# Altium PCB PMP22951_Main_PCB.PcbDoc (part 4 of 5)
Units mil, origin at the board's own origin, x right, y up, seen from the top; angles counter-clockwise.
Board outline 6643.5 x 4153.54 mil, 6 copper layers (Top Layer, Signal Layer 1, Signal Layer 2, Signal Layer 3, Signal Layer 4, Bottom Layer), stack 65.8 mil thick; 139 components, 80 nets, 687 pads, 417 vias.
Unrouted connection lines stored in the file: 2.
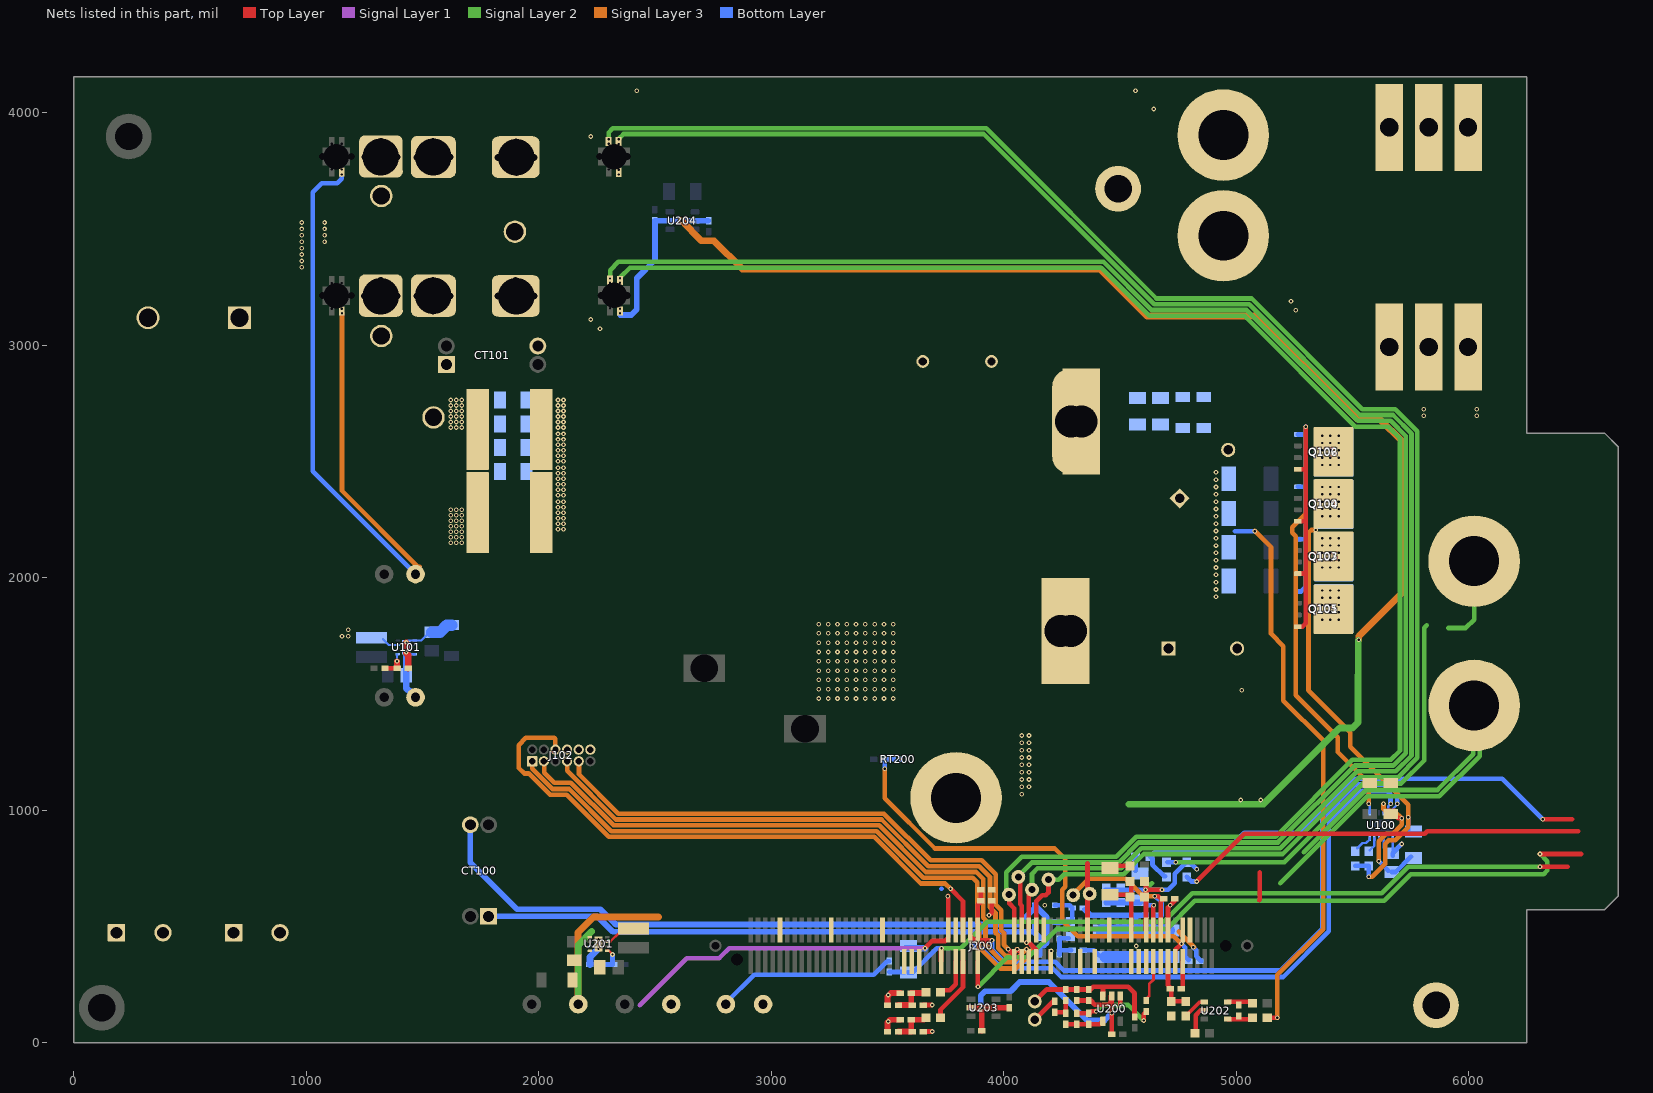
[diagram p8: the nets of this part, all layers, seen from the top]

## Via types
v1: diameter 20, hole 10, Top Layer to Bottom Layer, 409 vias
v2: diameter 19.68, hole 7.87, Top Layer to Bottom Layer, 7 vias
v3: diameter 24, hole 8, Top Layer to Bottom Layer, tented both sides, 1 vias

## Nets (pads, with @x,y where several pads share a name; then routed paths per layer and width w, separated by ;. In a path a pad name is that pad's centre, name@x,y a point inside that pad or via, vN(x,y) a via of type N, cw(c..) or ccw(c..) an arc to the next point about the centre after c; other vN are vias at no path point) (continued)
54V2: C115.1 Q100.5 Q100.6 Q100.7 Q100.8 Q100.9@5418.5,2316.93 Q101.5 Q101.6 Q101.7 Q101.8 Q101.9@5418.5,1864.17 Q102.5 Q102.6 Q102.7 Q102.8 Q102.9@5418.5,2541.34 Q103.5 Q103.6 Q103.7 Q103.8 Q103.9@5418.5,2092.52 Q104.5 Q104.6 Q104.7 Q104.8 Q104.9@5419.49,2315.32 Q105.5 Q105.6 Q105.7 Q105.8 Q105.9@5419.49,1865.32 Q106.5 Q106.6 Q106.7 Q106.8 Q106.9@5419.49,2540.32 Q107.5 Q107.6 Q107.7 Q107.8 Q107.9@5419.49,2090.32 R102.1 R108.2 R116.2 Vout+.1 | length 4053.5
  Signal Layer 2 w20: v1(4740,775) 5207.84,775 5547.46,1114.61 5710,1114.61 5808.77,1213.39 5808.77,1783.77 5820,1795 ; 5913.39,1783.46 5988.19,1783.46 6023.62,1818.9 Vout+.1@6023.62,1933.07
  Signal Layer 3 w20: v1(5342.52,2204.72) 5322.83,2204.72 5311.02,2192.91 5311.02,1515.75 5491.57,1335.2 5491.57,1272.21 5740.16,1023.62 v1(5740.16,968.5) 5740.16,926.38 5684.41,870.64 5656.85,870.64 5641.17,854.96 5641.17,768.34 5585.43,712.6 v1@5574.8,712.6
  Bottom Layer w20: R102.1@4705,775 v1(4740,775) ; R116.2@5511.81,759.84 C115.1@5562.99,759.84 ; v1(5570.87,712.6) C115.1@5570.87,759.84 ; R108.2@5740.16,909.45 v1(5740.16,968.5)
  other v1: 5370.08,1818.9 5405.51,1818.9 5440.94,1818.9 5370.08,1850.39 5405.51,1850.39 5440.94,1850.39 5370.08,1881.89 5405.51,1881.89 5440.94,1881.89 5370.08,1913.39 5405.51,1913.39 5440.94,1913.39 5370.08,1944.88 5405.51,1944.88 5440.94,1944.88 5370.08,2043.31 5405.51,2043.31 5440.94,2043.31 5370.08,2074.8 5405.51,2074.8 5440.94,2074.8 5370.08,2106.3 5405.51,2106.3 5440.94,2106.3 5370.08,2137.8 5405.51,2137.8 5440.94,2137.8 5370.08,2169.29 5405.51,2169.29 5440.94,2169.29 5370.08,2263.78 5405.51,2263.78 5440.94,2263.78 5370.08,2295.28 5405.51,2295.28 5440.94,2295.28 5370.08,2326.77 5405.51,2326.77 5440.94,2326.77 5370.08,2358.27 5405.51,2358.27 5440.94,2358.27 5370.08,2389.76 5405.51,2389.76 5440.94,2389.76 5370.08,2484.25 5405.51,2484.25 5440.94,2484.25 5370.08,2515.75 5405.51,2515.75 5440.94,2515.75 5370.08,2547.24 5405.51,2547.24 5440.94,2547.24 5370.08,2578.74 5405.51,2578.74 5440.94,2578.74 5370.08,2610.24 5405.51,2610.24 5440.94,2610.24
54VLS-EN: J200.58 | length 3027.1
  Top Layer w20: J200.58@3888.07,349.53 3888.07,241.85 v1(3889.76,240.16) ; v1(6307.09,811.02) 6484.25,811.02
  Signal Layer 2 w20: v1(3889.76,240.16) 4015.75,366.14 4106.3,366.14 4228.35,488.19 4700.79,488.19 4822.83,610.24 5637.8,610.24 5751.97,724.41 6322.83,724.41 6338.58,740.16 6338.58,779.53 v1(6307.09,811.02)
ACTIVE_EMI_SENSE_PSFB: J200.34
AD_IBUS: J200.24
COIL_SEC_N: C207.2 C209.1 pad.1@4133.86,177.17 R215.1 R219.2 U200.3 | length 597.2
  Top Layer w20: pad.1@4129.92,173.23 4185.04,228.35 C207.2@4267.72,228.35 C209.1@4314.96,228.35 4318.9,228.35 R219.2@4366.14,228.35 4374.02,228.35 4385.83,240.16 4535.43,240.16 4562.99,212.6 R215.1@4562.99,118.11 ; U200.3@4427.17,199.8 4427.17,230.32
COIL_SEC_P: pad.2 R217.1 | length 124.8
  Top Layer w20: pad.2@4129.92,94.49 4212.6,177.17 R217.1@4220.47,177.17
CS+: CT100.1 CT101.1 D201.2 D203.1 | length 2453.9
  Bottom Layer w25: CT100.1@1784.37,543.15 2252.13,543.15 2318.9,476.38 4129.92,476.38 4133.86,472.44 ; D201.2@4133.86,519.68 4133.86,472.44 ; D203.1@4153.54,452.76 4133.86,472.44
CS-: CT100.3 CT101.3 D200.2 D202.1 | length 2999.9
  Bottom Layer w25: CT100.3@1705,930 1705,775 1906.95,573.05 2264.51,573.05 2327.56,510 ; 2312.77,527.77 2332.15,508.38 4063.5,508.38 D200.2@4133.86,578.74 ; D200.2@4133.86,590.55 4185.54,538.87 4185.54,439.5 4184.85,438.81 4184.85,428.93 4173.43,417.51 4161.42,417.51 4153.54,409.63 D202.1@4153.54,377.95
DAC_OUT: J200.9
FAN_CTRL: J200.63
FAN_FB: J200.20
IHV_FB: C202.1 J200.15 pad.1@4299.21,633.86 R205.2 | length 710.4
  Top Layer w20: v1(4649.61,629.92) 4665.35,629.92 C202.1@4681.1,614.17 ; J200.15@4675.47,483.39 4675.47,604.61 C202.1@4685.04,614.17
  Signal Layer 3 w20: pad.1@4299.21,633.86 4299.21,637.8 4366.42,705 4525,705 4600,630 v1@4650,630
  Bottom Layer w20: v1(4649.61,629.92) 4652.36,629.92 4679.92,602.36 4679.92,545.08 4655.08,545.08 R205.2@4655,545
ILV_FB: C213.2 J200.14 R224.1 R227.2 | length 225.2
  Top Layer w20: J200.14@4706.97,349.53 4706.97,245.79 C213.2@4716.54,236.22 ; C213.2@4720.47,232.28 4720.47,181.1 4724.41,177.17 R224.1@4775.59,177.17
ILV_ZCD: J200.18 R218.2 | length 172.9
  Top Layer w12: R218.2@4614.17,188.98 4625.98,200.79 4625.98,251.97 4643.98,269.96 J200.18@4643.98,349.53
Iout_SNS: C110.1 C111.1 C117.1 C118.1 L100.2 pad.1@4334.33,2671.85 R100.1 R101.1 R103.2 R104.2 R105.1 R106.1 R226.1 | length 2426.6
  Top Layer w20: R226.1@5133.86,106.3 v1(5177.17,106.3)
  Signal Layer 3 w20: v1@5079.93,2200.79 5150.17,2130.55 5150.17,1758.21 5203.02,1705.35 5203.02,1471.01 5374.57,1299.46 5374.57,488.19 5177.17,290.78 v1(5177.17,106.3)
  Bottom Layer w20: 4995,2200 v1(5080,2200)
  other v1: 4913.39,1917.32 4913.39,1948.82 4913.39,1980.32 4913.39,2011.81 4913.39,2043.31 4913.39,2074.8 4913.39,2106.3 4913.39,2137.8 4913.39,2169.29 4913.39,2200.79 4913.39,2232.28 4913.39,2263.78 4913.39,2295.28 4913.39,2326.77 4913.39,2358.27 4913.39,2389.76 4913.39,2421.26 4913.39,2452.76
LEG1_FLT: R200.2 | length 39.4
  Top Layer w20: R200.2@3653.54,47.24 v1(3692.91,47.24)
LEG1_HS: J200.49 pad.1@2300.65,3866.04 pad.1@4192.91,700.79 | length 7500.6
  Top Layer w20: J200.49@4140.04,483.39 4140.04,608.54 4165.35,633.86 4181.1,633.86 4192.91,645.67 pad.1@4192.91,688.98
  Signal Layer 2 w20: v1(2300.65,3886.16) 2300.65,3914.82 2318.9,3933.07 3925.2,3933.07 4657.48,3200.79 5066.93,3200.79 5543.31,2724.41 5685.04,2724.41 5779.53,2629.92 5779.53,1224.41 5696.85,1141.73 5531.5,1141.73 5200.79,811.02 4602.36,811.02 4515.75,724.41 4259.84,724.41 4236.22,700.79 pad.1@4192.91,700.79
LEG1_LS: J200.51 pad.1@2343.7,3865.04 pad.1@4122.05,657.48 | length 7421.6
  Top Layer w20: J200.51@4108.54,483.39 pad.1@4108.54,636.1
  Signal Layer 2 w20: pad.1@2346.46,3889.76 2364.86,3908.17 3914.88,3908.17 4647.17,3175.89 5056.62,3175.89 5532.99,2699.51 5674.73,2699.51 5754.63,2619.61 5754.63,1234.72 5686.54,1166.63 5520.96,1166.63 5190.25,835.92 4592.05,835.92 4505.43,749.31 4145.67,749.31 4122.05,725.69 pad.1@4122.05,657.48 pad.1@4114.17,648.01 ; pad.1@4110.24,637.8 pad.1@4120.71,637.8
  other v1: 2343.7,3885.16
LEG2_FLT: R203.2 | length 35.4
  Top Layer w20: R203.2@3653.54,161.42 v1@3688.98,161.42
  other v1: 3692.91,161.42
LEG2_HS: J200.53 pad.1@2306.65,3269.04 pad.1@4062.99,712.6 | length 7255.3
  Top Layer w20: pad.1@4070.87,704.72 4070.87,594.49 4077.05,588.31 J200.53@4077.05,483.39
  Signal Layer 2 w20: pad.1@2307.09,3287.4 2307.09,3322.83 2342.74,3358.49 4429.35,3358.49 4636.85,3150.99 5046.3,3150.99 5522.68,2674.61 5664.41,2674.61 5729.73,2609.29 5729.73,1245.04 5676.22,1191.53 5510.65,1191.53 5179.94,860.82 4581.3,860.82 4494.68,774.21 4120.67,774.21 pad.1@4066.93,720.47 ; pad.1@4062.99,712.6 pad.1@4066.93,712.6
  other v3: 2306.74,3287.16
LEG2_LS: J200.55 pad.1@2349.7,3268.04 pad.1@4022.28,636.06 | length 7187.3
  Top Layer w20: pad.1@4019.69,625.98 4023.62,622.05 4023.62,598.43 4045.55,576.5 J200.55@4045.55,483.39
  Signal Layer 2 w20: pad.1@2350.39,3291.34 2392.64,3333.59 4419.04,3333.59 4626.54,3126.09 5035.99,3126.09 5512.37,2649.71 5654.1,2649.71 5704.83,2598.98 5704.83,1255.35 5665.91,1216.43 5500.34,1216.43 5169.63,885.72 4570.98,885.72 4484.37,799.11 4078.64,799.11 4011.81,732.28 4011.81,646.54 pad.1@4022.28,636.06 ; pad.1@4027.56,653.54 pad.1@4031.5,653.54
  other v1: 2349.7,3288.16
LEG3_HS: J102.1 J200.50 | length 2892.4
  Top Layer w20: v1(4098.43,429.13) 4110.24,429.13 4140.04,399.33 J200.50@4140.04,349.53
  Signal Layer 3 w20: J102.1@1972.44,1212.6 1972.44,1177.38 2058.95,1090.88 2130.25,1090.88 2311.58,909.55 3453.97,909.55 3654.76,708.76 3866.14,708.76 3885.83,689.08 3885.83,519.68 3894,511.51 3894,409.88 3985.31,318.57 4053.61,318.57 4054.61,319.57 4054.84,319.57 4085.13,349.87 ; 4085.02,349.98 4125.43,390.39 4125.43,412.76 4109.05,429.13 v1(4098.43,429.13)
LEG3_LS: J102.3 J200.52 | length 2698
  Top Layer w20: J200.52@4099.05,402.13 4108.54,392.64 J200.52@4108.54,349.53
  Signal Layer 3 w20: J102.3@2022.05,1208.66 J102.3@2022.05,1210 ; J102.3@2023.62,1208.66 2023.62,1161.42 2066.93,1118.11 2138.23,1118.11 2321.89,934.45 3464.29,934.45 3665.07,733.66 3881.89,733.66 3912.11,703.45 3912.11,536.93 3922,527.04 3922,421.48 3996.9,346.57 4042.01,346.57 ; 4043.24,347.57 4097.24,401.57 v1(4098.43,401.57)
LEG4_HS: J102.7 J200.54 | length 2537
  Top Layer w20: v1(4059.06,401.57) 4077.05,383.58 J200.54@4077.05,349.53
  Signal Layer 3 w20: J102.7@2122.05,1210 2122.05,1169.51 2332.21,959.35 3474.6,959.35 3675.39,758.56 3894.98,758.56 3940.94,712.6 3940.94,582.68 3964.57,559.06 3964.57,472.44 3976.38,460.63 3976.38,405.51 4007.87,374.02 4031.5,374.02 v1(4059.06,401.57)
LEG4_LS: J102.9 J200.56 | length 2434
  Top Layer w20: v1(4019.69,401.57) 4045.55,375.71 J200.56@4045.55,349.53
  Signal Layer 3 w20: J102.9@2172.05,1208.66 J102.9@2172.05,1210 ; J102.9@2173.23,1208.66 2173.23,1153.54 2342.52,984.25 3484.91,984.25 3685.7,783.46 3905.51,783.46 3965.84,723.13 3965.84,593.21 3989.47,569.59 3989.47,482.97 4001.28,471.16 4001.28,419.98 v1(4019.69,401.57)
NetC113_1: C113.1 C114.1 R108.1 U100.4 U100.10 | length 697.4
  Top Layer w20: C113.1@5677.17,984.25 5696.85,964.57 v1(5712.6,964.57)
  Signal Layer 3 w20: v1(5614.17,779.53) 5614.17,866.14 5645.67,897.64 5673.23,897.64 5712.6,937.01 v1(5712.6,964.57) 5681.1,996.06 5641.73,996.06 5633.86,1003.94 v1(5633.86,1027.56)
  Bottom Layer w10: v1@5614.45,779.25 U100.10@5614.45,879.02 ; U100.4@5634.13,988.46 5634.13,1016.41
  Bottom Layer w20: v1(5614.17,779.53) 5614.45,779.25 C114.1@5653.54,740.16 ; C114.1@5669.29,733.74 5686.5,733.74 R108.1@5751.97,799.21
NetC115_2: C115.2 U100.11 | length 60.5
  Bottom Layer w10: C115.2@5574.8,826.77 5594.76,846.73 U100.11@5594.76,879.02
NetC200_1: C200.1 R200.1 R201.2 R202.2 | length 153.5
  Top Layer w25: R202.2@3547.24,47.24 3574.8,47.24 R200.1@3602.36,47.24 ; R200.1@3602.36,55.12 C200.1@3602.36,98.43 R201.2@3657.48,98.43
NetC201_1: C201.1 R203.1 R204.2 R207.2 | length 153.5
  Top Layer w25: R207.2@3547.24,161.42 3574.8,161.42 3602.36,161.42 C201.1@3602.36,204.72 ; C201.1@3602.36,212.6 R204.2@3657.48,212.6
NetC203_1: C203.1 J200.57 R211.2 | length 175.8
  Top Layer w20: J200.57@3888.07,483.39 3888.07,592.8 3901.57,606.3 R211.2@3901.57,653.54
NetC204_1: C204.1 R214.2 R218.1 U200.1 | length 404.9
  Top Layer w20: R214.2@4314.96,125.98 4370.08,125.98 4377.95,133.86 v1(4397.64,133.86) ; v1@4501.97,163.39 U200.1@4501.97,199.8 ; v1(4602.36,94.49) 4602.36,122.05 R218.1@4610.24,129.92
  Signal Layer 2 w20: v1(4397.64,133.86) 4425.2,161.42 v1(4503.94,161.42) 4535.43,161.42 v1(4602.36,94.49)
NetC204_2: C204.2 R214.1 R216.2 U200.4 | length 164.7
  Top Layer w20: R216.2@4267.72,78.74 R214.1@4322.83,78.74 ; R214.1@4314.96,78.74 4413.39,78.74 U200.4@4421.26,86.61
NetC207_1: C207.1 R216.1 R217.2 | length 94.5
  Top Layer w20: R217.2@4220.47,129.92 R216.1@4263.78,129.92 ; R216.1@4267.72,129.92 C207.1@4267.72,181.1
NetC212_1: C212.1 R223.2 U202.5 | length 109.3
  Top Layer w20: U202.5@4963.58,175.2 R223.2@5072.83,175.2
NetC212_2: C212.2 R226.2 U202.4 | length 105.3
  Top Layer w20: U202.4@4963.58,100.39 R226.2@5068.9,100.39
NetD200_1: D200.1 D201.1 R206.1 R210.1 | length 201.7
  Bottom Layer w19.68: D201.1@4220.47,519.68 4220.47,515.75 R210.1@4283.46,515.75 ; D200.1@4220.47,590.55 4283.46,590.55 R206.1@4295.28,578.74 R210.1@4295.28,523.62
NetD202_2: D202.2 D203.2 R210.2 R212.1 | length 153.5
  Bottom Layer w19.68: D202.2@4240.16,377.95 D203.2@4240.16,444.88 ; D203.2@4240.16,448.82 R210.2@4279.53,448.82 ; 4244.09,397.64 R212.1@4291.34,397.64
NetJ200_62: J200.62 R201.1 | length 275.4
  Top Layer w20: R201.1@3728.35,114.17 3728.35,141.73 3825.08,238.46 J200.62@3825.08,349.53
NetJ200_64: J200.64 R204.1 | length 163.4
  Top Layer w20: R204.1@3740.16,224.41 3767.72,224.41 3793.58,250.28 J200.64@3793.58,349.53
NetL103_1: L103.1 U101.7 | length 73
  Bottom Layer w10: L103.1@1330,1735 1355.16,1709.84 U101.7@1392.6,1709.84
NetL200_1: L200.1 U201.7 | length 69.2
  Top Layer w10: U201.7@2294.57,433.78 2307.01,433.78 L200.1@2347.17,473.94
NetPSON_1: PSON.1 R233.1 | length 777.6
  Bottom Layer w20: PSON.1@2805,170 2926.34,291.34 3440.94,291.34 3500,350.39 R233.1@3507.87,350.39
NetQ100_4: Q100.4 Q101.4 Q102.4 Q103.4 Q104.4 Q105.4 Q106.4 Q107.4 U100.1 | length 3622
  Top Layer w20: Q101.4@5261.81,1789.37 5285.43,1789.37 5298.89,1802.83 v1@5298.89,2649.28 ; Q103.4@5264.96,2017.52 5293.11,2017.52 ; Q100.4@5264.96,2241.93 5293.11,2241.93 ; Q102.4@5264.96,2466.34 5295.08,2466.34
  Signal Layer 3 w20: v1(5299.21,2649.61) 5299.21,2274.4 5240.72,2215.91 5240.72,2193.47 5257.02,2177.17 5257.02,1493.38 5437.57,1312.84 5437.57,1249.85 5570.87,1116.55 v1(5570.87,1027.56)
  Bottom Layer w10: v1@5566.93,1027.56 5575.08,1019.41 U100.1@5575.08,988.46
  Bottom Layer w20: Q105.4@5265.94,1940.32 5278.9,1940.32 5299.87,1961.29 v1@5299.87,2650.27 ; Q107.4@5265.94,2165.32 5295.24,2165.32 ; Q104.4@5265.94,2390.32 5295.83,2390.32 ; Q106.4@5265.94,2615.31 5296.1,2615.31
NetR116_1: R116.1 U100.12 | length 76.5
  Bottom Layer w10: R116.1@5519.69,834.65 5543.31,858.27 5559.06,858.27 5574.8,874.02 5574.8,878.74 U100.12@5575.08,879.02
NetR120_1: R120.1 R121.2 U101.5 | length 106.4
  Top Layer w20: R120.1@1340,1610 R121.2@1391.38,1610
  Top Layer w25: R121.2@1390,1615 v1(1390,1640)
  Bottom Layer w10: v1(1390,1640) U101.5@1390,1670
NetR205_1: R205.1 R206.2 R208.2 R209.2 R234.2 R235.2 | length 625.5
  Bottom Layer w20: 4570,482.09 4570,545
  Bottom Layer w25: R206.2@4350.39,570.87 4374.02,547.24 R205.1@4610.24,547.24
  Bottom Layer w50: R209.2@4420,482.09 R208.2@4520,482.09 4570,482.09 R234.2@4620,482.09 R235.2@4712.91,482.09
NetR220_2: R220.2 R221.1 | length 59.1
  Bottom Layer w20: R220.2@4566.93,740.16 R221.1@4566.93,799.21
NetR224_2: R224.2 U202.1 | length 103.2
  Top Layer w16: R224.2@4783.46,114.17 4842.52,173.23 U202.1@4862.2,173.23
NetR228_2: R228.2 R229.1 | length 74.8
  Top Layer w20: R228.2@4468.5,759.84 R229.1@4543.31,759.84
NetR230_1: R230.1 R232.2 U201.5 | length 122.1
  Top Layer w10: U201.5@2294.57,394.41 2301.69,394.41 v1(2317.17,378.94)
  Bottom Layer w20: R232.2@2267.28,335.71 R230.1@2318.46,335.71 ; R230.1@2317.17,337.01 v1(2317.17,378.94)
NetT100_1: 
NetT100_2: 
ORING_EN: J200.59 U100.6 | length 2669.2
  Top Layer w20: J200.59@3856.57,483.39 3856.57,458.43 3875,440 v1(3950,440)
  Bottom Layer w10: U100.6@5673.5,988.46 5673.5,1004.21 v1@5696.85,1027.56
  Bottom Layer w20: v1(3950,440) 3950,400 4002.55,347.45 4221.6,347.45 4259.05,310 5190.4,310 5370,489.6 5370,965 5515,1110 5659.6,1110 5692.35,1077.24 5692.35,1050 ; v1@5692.35,1028.12 v1(5692.91,1027.56) ; v1@5693.35,1026.65 5693.35,1050
PGND: C100.2 C101.2 C102.2 C103.2 C104.2 C105.1 C106.1 C116.1 C123.2 C124.2 C125.2 pad.1@1152.84,3156.85 pad.1@1152.84,3755.28 pad.1@1475.74,3211.16 pad.1@1475.74,3808.16 pad.1@1544.74,3278.16 pad.1@1544.74,3875.16 pad.1@1545.74,3147.16 pad.1@1545.74,3744.16 pad.1@1546.74,3212.16 pad.1@1546.74,3809.16 pad.1@1618.74,3212.16 pad.1@1618.74,3809.16 PGND.1 PGND.2 R121.1 U101.1 U101.4 U101.9@1430,1700 | length 3758.6
  Top Layer w29.53: v2@1430,1720 v2(1430,1678.35) 1430,1675 1438.62,1666.38 R121.1@1438.62,1610
  Signal Layer 1 w20: PGND.1@1461.38,2015 PGND.1@1470,2015
  Signal Layer 3 w20: v1(1153.54,3137.8) 1153.54,2374.02 1480.31,2047.24 PGND.1@1488.19,2047.24
  Bottom Layer w10: U101.9@1435,1670 1466.93,1670 U101.4@1467.4,1670.47 ; U101.9@1435,1725 1439.53,1729.53 U101.1@1467.4,1729.53 1494.53,1729.53 C123.2@1520,1755
  Bottom Layer w20: v1(1152.84,3734.16) 1152.84,3715.83 1133.86,3696.85 1066.93,3696.85 1027.56,3657.48 1027.56,2457.44 PGND.1@1470,2015
  Bottom Layer w29.53: v2(1430,1678.35) 1430,1525 PGND.1@1450,1505
  Bottom Layer w50: C123.2@1540,1765 1575,1765 1605,1795 C125.2@1625,1795
  other v1: 1153.54,1748.03 1181.1,1748.03 1181.1,1775.59 2082.68,2208.66 2106.3,2208.66 2082.68,2232.28 2106.3,2232.28 2082.68,2255.91 2106.3,2255.91 2082.68,2279.53 2106.3,2279.53 2082.68,2303.15 2106.3,2303.15 2082.68,2326.77 2106.3,2326.77 2082.68,2354.33 2106.3,2354.33 2082.68,2377.95 2106.3,2377.95 2082.68,2401.57 2106.3,2401.57 2082.68,2425.2 2106.3,2425.2 2082.68,2448.82 2106.3,2448.82 2082.68,2472.44 2106.3,2472.44 2082.68,2500 2106.3,2500 2082.68,2523.62 2106.3,2523.62 2082.68,2547.24 2106.3,2547.24 2082.68,2570.87 2106.3,2570.87 2082.68,2594.49 2106.3,2594.49 2082.68,2618.11 2106.3,2618.11 2082.68,2645.67 2106.3,2645.67 2082.68,2669.29 2106.3,2669.29 2082.68,2692.91 2106.3,2692.91 2082.68,2716.54 2106.3,2716.54 2082.68,2740.16 2106.3,2740.16 2082.68,2763.78 2106.3,2763.78 980.32,3334.65 980.32,3362.2 980.32,3389.76 980.32,3417.32 980.32,3444.88 1078.74,3444.88 980.32,3472.44 1078.74,3472.44 980.32,3500 1078.74,3500 980.32,3527.56 1078.74,3527.56
  other v2: 1430,1721.65
PRI_FAULT_SEC: J200.74
PSFB_ON: J200.68 R225.2 R233.2 | length 3144.2
  Top Layer w20: J200.68@3730.59,349.53 v1@3730.59,403.82 ; v1(6307.09,755.91) 6425.2,755.91
  Signal Layer 2 w20: v1(3732.28,405.51) 3814.96,405.51 3929.13,519.68 4688.98,519.68 4811.02,641.73 5625.98,641.73 5740.16,755.91 v1(6307.09,755.91)
  Bottom Layer w20: R233.2@3507.87,303.15 R225.2@3574.8,303.15 ; R225.2@3590.55,301.18 3608.27,301.18 3712.6,405.51 v1(3732.28,405.51)
PWM_ACL: J102.6 J200.61 | length 2583.6
  Top Layer w20: v1(3771.65,661.42) 3825.08,607.99 J200.61@3825.08,483.39
  Signal Layer 3 w20: J102.6@2070.87,1267.72 2070.87,1307.09 2066.93,1311.02 1944.88,1311.02 1913.39,1279.53 1913.39,1181.1 1937.01,1157.48 1957.13,1157.48 2048.63,1065.98 2119.94,1065.98 2301.26,884.65 3443.66,884.65 3644.44,683.86 3749.21,683.86 v1(3771.65,661.42)
PWM_DEBUG_SEC: R211.1
SEC_SCI_RX0: J200.76
SEC_SCI_TX0: J200.78
SGND: C110.2 C111.2 C112.1 C113.2 C114.2 C116.2 C117.2 C118.2 C200.2 C201.2 C202.2 C203.2 C205.2 C206.2 C208.2 C209.2 C210.2 C211.1 C213.1 C214.2 C215.2 C216.2 C217.2 C218.2 C219.2 C220.2 J102.8 J102.10 J102.12 J200.7 J200.10 J200.13 J200.16 J200.19 J200.22 J200.29 J200.35 J200.38 J200.46 J200.47 J200.65 J200.83 J200.97 J200.111 pad.1@2343.84,3754.28 pad.1@2349.84,3157.28 pad.1@4370,640 pad.1@4492.13,3673.23 pad.1@5860,160 R103.1 R104.1 R107.1 R202.1 R207.1 R208.1 R209.1 R212.2 R219.1 R222.1 R225.1 R227.1 R231.1 R232.1 R234.1 R235.1 RT200.1 SGND.1 U100.5 U100.7 U100.9 U200.2 U201.1 U201.4 U201.9@2257.17,423.94 U202.2 U203.2 U204.2 Vout-.1 | length 18183.9
  Top Layer w20: v1(3661.42,405.51) 3692.91,437.01 3748.03,437.01 3762.09,451.06 J200.65@3762.09,483.39 v1@3762.09,631.61 ; v1(3937.01,547.24) 3948.82,559.06 C203.2@3948.82,610.24 ; J200.46@4203.03,349.53 J200.46@4203.03,392.01 ; C209.2@4314.96,181.1 4374.02,181.1 4392,163.12 4450.52,163.12 4460.63,173.23 4460.63,200.79 U200.2@4464.57,204.72 ; J200.35@4360.51,483.39 4360.51,769.96 4362.2,771.65 ; C206.2@4464.57,39.37 U200.2@4464.57,199.8 ; v1(4610.24,657.48) v1@4612.48,657.48 ; R231.1@4610.24,696.85 4612.48,694.61 v1@4612.48,657.48 ; J200.19@4612.48,483.39 v1@4612.48,657.48 ; v1(4681.1,657.48) v1@4612.48,657.48 ; J200.13@4706.97,483.39 4706.97,580.98 C202.2@4736.22,610.24 ; C213.1@4769.96,238.46 J200.10@4769.96,349.53 ; C211.1@4826.77,47.24 4826.77,118.11 4846.46,137.8 U202.2@4863.19,137.8 ; 5098.86,611.89 5101.46,614.49 5101.46,731.69
  Top Layer w25: R202.1@3500,51.18 3500,86.61 3511.81,98.43 C200.2@3555.12,98.43 ; R207.1@3500,165.35 3500,196.85 3515.75,212.6 C201.2@3555.12,212.6 ; U203.2@3859.25,149.61 v1(3905.51,149.61) C217.2@4023.62,149.61 ; C218.2@3905.51,51.18 v1@3905.51,145.67
  Signal Layer 1 w20: 2435,160 2637.2,362.2 2775.59,362.2 2783.46,370.08 2818.9,405.51 v1(3661.42,405.51)
  Signal Layer 2 w20: v1(4610.24,657.48) 4637.8,685.04 ; 5190.16,685.04 5564.18,1059.06 5594.49,1059.06 5874.02,1059.05 6047.24,1232.28 Vout-.1@6047.24,1381.89 ; 5291.34,818.9 5559.06,1086.61 5866.14,1086.61 6019.69,1240.16 Vout-.1@6019.69,1354.33
  Signal Layer 2 w29.53: SGND.1@2170,165 2170,419.53 2227.91,477.44 ; 4538.55,1025.29 5117.89,1025.29 5445.51,1352.91 5500.46,1352.91 5524.48,1376.92 5524.48,1580 ; 5525.48,1580 v1@5525.48,1730.2
  Signal Layer 3 w20: 4752.5,477.5 v1@4820,410
  Signal Layer 3 w29.53: SGND.1@2170,165 SGND.1@2170,177.09 ; SGND.1@2180.67,166.42 SGND.1@2170,177.09 ; 2515.32,540.43 2235.79,540.43 2168.86,473.5 2168.86,178.23 SGND.1@2170,177.09 ; v1(2614.17,3535.43) 2700.79,3448.82 2754.46,3448.82 2875.5,3327.78 4414.87,3327.78 4616.67,3125.98 5078.74,3125.98 5523.62,2681.1 5618.11,2681.1 5712.6,2586.61 5712.6,1933.07 5527.56,1748.03 v1(5527.56,1732.28)
  Bottom Layer w10: U100.9@5634.13,879.02 5634.13,838.31 C114.2@5641.73,830.71 ; U100.5@5653.82,988.46 5653.82,1015.47 5669.29,1030.94 v1@5669.29,1031.5 ; C114.2@5673.23,818.9 5673.5,819.17 U100.7@5673.5,879.02
  Bottom Layer w20: 3732.28,661.42 3732.28,661.65 ; v1(3860,415) 3895.4,415 3990.95,319.45 4210,319.45 4247.45,282 5202,282 5398,478 5398,953.4 5526.6,1082 5648,1082 5664.35,1065.65 v1@5664.35,1027.59 ; R212.2@4342.52,397.64 4387.36,397.64 R209.1@4410,375 ; R222.1@4437.01,657.48 v1(4610.24,657.48) v1(4681.1,657.48) ; v1@4685.04,657.48 4708.66,657.48 4736.49,685.31 4736.49,726.49 R107.1@4785,775 ; R107.1@4787.4,775.59 4799.41,775.59 v1(4830,745) ; v1(4815,410) 4828.62,396.38 4828.62,371.38 C205.2@4850,350 ; C114.2@5673.23,803.15 5673.23,814.96 v1(5712.6,854.33)
  Bottom Layer w25: pad.1@2350.39,3129.92 2397.64,3129.92 2421.26,3153.54 2421.26,3288.02 2500,3366.76 C208.2@2500,3535.43 C220.2@2728.35,3535.43 ; v1(3905.51,149.61) 3901.07,154.05 3901.07,202.23 3919.82,220.98 4030.05,220.98 4069.42,260.35 4194.36,260.35 4359.71,94.99 4433.57,94.99 v1(4464.57,125.98)
  Bottom Layer w29.53: R232.1@2220.04,335.71 2220.04,367.2 v2@2255.47,402.64 ; R225.1@3578.74,405.51 v1(3661.42,405.51)
  Bottom Layer w50: R209.1@4437.91,367.91 R208.1@4520,367.91 R234.1@4620,367.91 R235.1@4720,367.91
  other v1: 3503.94,90.55 3503.94,204.72 4204.72,393.7 4570,415 4177.17,590.55 4716.54,590.55 3759.84,629.92 5665.35,1027.56 5019.69,1043.31 5106.3,1043.31 4077.36,1068.7 4077.36,1100.2 4108.86,1100.2 4077.36,1131.69 4108.86,1131.69 4077.36,1163.19 4108.86,1163.19 4077.36,1194.68 4108.86,1194.69 4077.36,1226.18 4108.86,1226.18 4077.36,1257.68 4108.86,1257.68 4077.36,1289.17 4108.86,1289.17 4077.36,1320.67 4108.86,1320.67 5023.62,1515.75 5807.09,2696.85 6035.43,2696.85 5807.09,2724.41 6035.43,2724.41 2263.78,3070.87 2224.41,3110.24 2349.84,3137.16 5255.91,3149.61 5236.22,3188.98 2343.84,3734.16 2224.41,3897.64 4645.67,4015.75 2421.26,4094.49 4566.93,4094.49
  other v2: 2257.17,402.28 2257.17,445.59
SWNODE1: pad.1@1251.74,3810.16 pad.1@1319.71,3809.57 pad.1@1320.74,3877.16 pad.1@1321.74,3746.16 pad.1@1389.74,3810.16 TP108.1
SWNODE2: pad.1@1250.74,3211.16 pad.1@1251.74,3211.73 pad.1@1319.71,3210.57 pad.1@1319.71,3211.15 pad.1@1319.74,3278.16 pad.1@1320.74,3147.16 pad.1@1320.74,3278.73 pad.1@1321.74,3147.73 pad.1@1388.74,3211.16 pad.1@1389.74,3211.73 TP100.1
SWNODE3: pad.1@4944.88,3903.82 pad.1@5659.21,3937.05 pad.1@5828.5,2992.17 pad.1@5997.8,3937.05
SWNODE4: pad.1@4944.88,3470.75 pad.1@5659.21,2992.17 pad.1@5828.5,3937.05 pad.1@5997.8,2992.17
TMP_SEC: C205.1 J200.12 R213.2 RT200.2 | length 2063.9
  Top Layer w20: J200.12@4738.46,349.53 4738.46,398.46 v1(4765,425)
  Signal Layer 3 w19.68: v1(3488.19,1177.17) 3488.19,1051.18 3704.72,834.65 4220.03,834.65 4264.9,789.78 4264.9,670.85 4251.97,657.92 4251.97,523.62 4318.9,456.69 4732.28,456.69 v1@4763.78,425.2 ; v1@4764.29,425.71 v1(4765,425)
  Bottom Layer w19.68: v1(3488.19,1177.17) R213.2@3488.19,1216.54
  Bottom Layer w20: 3504.41,1218.62 3523.98,1218.62 ; v1(4765,425) 4781.38,408.62 4781.38,368.62 C205.1@4795,355
VBB: C100.1 C101.1 C102.1 C103.1 C104.1 C105.2 C106.2 TP109.1 Vin.1 Vin.2
  other v1: 1622.05,2149.61 1645.67,2149.61 1669.29,2149.61 1622.05,2173.23 1645.67,2173.23 1669.29,2173.23 1622.05,2196.85 1645.67,2196.85 1669.29,2196.85 1622.05,2220.47 1645.67,2220.47 1669.29,2220.47 1622.05,2244.09 1645.67,2244.09 1669.29,2244.09 1622.05,2267.72 1645.67,2267.72 1669.29,2267.72 1622.05,2291.34 1645.67,2291.34 1669.29,2291.34 1622.05,2645.67 1645.67,2645.67 1669.29,2645.67 1622.05,2669.29 1645.67,2669.29 1669.29,2669.29 1622.05,2692.91 1645.67,2692.91 1669.29,2692.91 1622.05,2716.54 1645.67,2716.54 1669.29,2716.54 1622.05,2740.16 1645.67,2740.16 1669.29,2740.16 1622.05,2763.78 1645.67,2763.78 1669.29,2763.78
VBB1: pad.1@1823.74,3211.16 pad.1@1823.74,3808.16 pad.1@1900.74,3277.16 pad.1@1901.74,3146.16 pad.1@1902.74,3211.16 pad.1@1902.74,3808.16 pad.1@1902.74,3874.16 pad.1@1903.74,3743.16 pad.1@1978.74,3211.16 pad.1@1978.74,3808.16 TP110.1
VLV_FB: C214.1 J200.23 R228.1 R231.2 | length 299.8
  Top Layer w20: R228.1@4456.69,635.83 C214.1@4545.28,635.83 ; J200.23@4549.49,483.39 R231.2@4549.49,694.61
VLV_FB1: C210.1 J200.17 R220.1 R222.2 | length 291.8
  Top Layer w20: J200.17@4643.98,483.39 4643.98,588.98 v1(4645,590)
  Bottom Layer w20: R220.1@4610,600 4620,590 v1(4645,590)
  Bottom Layer w25: R222.2@4440.94,602.36 R220.1@4586.61,602.36
Vout_SNS+: R102.2 R221.2 | length 2136.8
  Top Layer w20: v1(6318.9,960.63) 6444.88,960.63
  Bottom Layer w20: R221.2@4629.92,799.21 4649.61,818.9 4952.76,818.9 5035.43,901.57 5271.36,901.57 5504.69,1134.9 6144.63,1134.9 v1(6318.9,960.63) ; R221.2@4629.92,803.15 R221.2@4631.89,801.18 ; R221.2@4635,795 4640,790 4640,765 4690,715 R102.2@4695,715
Vout_SNS-: R107.2 | length 1782.9
  Top Layer w20: v1(4830.71,692.91) 5035.43,897.64 5811.02,897.64 5822.83,909.45 6472.44,909.45
  Bottom Layer w20: R107.2@4787.4,712.6 4807.09,692.91 v1(4830.71,692.91)
VSR: L100.1 pad.1@4243.78,1770.28
  other v1: 3205,1480 3245,1480 3285,1480 3325,1480 3365,1480 3405,1480 3445,1480 3485,1480 3525,1480 3205,1520 3245,1520 3285,1520 3325,1520 3365,1520 3405,1520 3445,1520 3485,1520 3525,1520 3205,1560 3245,1560 3285,1560 3325,1560 3365,1560 3405,1560 3445,1560 3485,1560 3525,1560 3205,1600 3245,1600 3285,1600 3325,1600 3365,1600 3405,1600 3445,1600 3485,1600 3525,1600 3205,1640 3245,1640 3285,1640 3325,1640 3365,1640 3405,1640 3445,1640 3485,1640 3525,1640 3205,1680 3245,1680 3285,1680 3325,1680 3365,1680 3405,1680 3445,1680 3485,1680 3525,1680 3205,1720 3245,1720 3285,1720 3325,1720 3365,1720 3405,1720 3445,1720 3485,1720 3525,1720 3205,1760 3245,1760 3285,1760 3325,1760 3365,1760 3405,1760 3445,1760 3485,1760 3525,1760 3205,1800 3245,1800 3285,1800 3325,1800 3365,1800 3405,1800 3445,1800 3485,1800 3525,1800
pads on no net: CT100.2 CT100.4 CT101.2 CT101.4 J200.1 J200.2 J200.3 J200.4 J200.5 J200.6 J200.8 J200.11 J200.21 J200.25 J200.26 J200.27 J200.28 J200.30 J200.31 J200.32 J200.33 J200.36 J200.37 J200.39 J200.40 J200.41 J200.42 J200.43 J200.44 J200.45 J200.48 J200.60 J200.66 J200.67 J200.69 J200.70 J200.71 J200.72 J200.73 J200.75 J200.77 J200.79 J200.80 J200.81 J200.82 J200.85 J200.86 J200.87 J200.88 J200.89 J200.90 J200.91 J200.92 J200.93 J200.94 J200.95 J200.96 J200.99 J200.100 J200.101 J200.102 J200.103 J200.104 J200.105 J200.106 J200.107 J200.108 J200.109 J200.110 J200.113 J200.114 J200.115 J200.116 J200.117 J200.118 J200.119 J200.120 J200.181 J200.182 J200.185 J200.186 Q100.9@5343.31,2223.52 Q100.9@5343.31,2410.33 Q100.9@5354.92,2264.57 Q100.9@5354.92,2316.93 Q100.9@5354.92,2369.29 Q100.9@5400.2,2264.57 Q100.9@5400.2,2316.93 Q100.9@5400.2,2369.29 Q100.9@5405.51,2316.93 Q100.9@5445.47,2264.57 Q100.9@5445.47,2316.93 Q100.9@5445.47,2369.29 Q101.9@5343.31,1770.77 Q101.9@5343.31,1957.58 Q101.9@5354.92,1811.81 Q101.9@5354.92,1864.17 Q101.9@5354.92,1916.54 Q101.9@5400.2,1811.81 Q101.9@5400.2,1864.17 Q101.9@5400.2,1916.54 Q101.9@5405.51,1864.17 Q101.9@5445.47,1811.81 Q101.9@5445.47,1864.17 Q101.9@5445.47,1916.54 Q102.9@5343.31,2447.93 Q102.9@5343.31,2634.74 Q102.9@5354.92,2488.98 Q102.9@5354.92,2541.34 Q102.9@5354.92,2593.7 Q102.9@5400.2,2488.98 Q102.9@5400.2,2541.34 Q102.9@5400.2,2593.7 Q102.9@5405.51,2541.34 Q102.9@5445.47,2488.98 Q102.9@5445.47,2541.34 Q102.9@5445.47,2593.7 Q103.9@5343.31,1999.11 Q103.9@5343.31,2185.93 Q103.9@5354.92,2040.16 Q103.9@5354.92,2092.52 Q103.9@5354.92,2144.88 Q103.9@5400.2,2040.16 Q103.9@5400.2,2092.52 Q103.9@5400.2,2144.88 Q103.9@5405.51,2092.52 Q103.9@5445.47,2040.16 Q103.9@5445.47,2092.52 Q103.9@5445.47,2144.88 Q104.9@5344.29,2221.91 Q104.9@5344.29,2408.72 Q104.9@5355.91,2262.95 Q104.9@5355.91,2315.32 Q104.9@5355.91,2367.68 Q104.9@5401.18,2262.95 Q104.9@5401.18,2315.32 Q104.9@5401.18,2367.68 Q104.9@5406.5,2315.32 Q104.9@5446.46,2262.95 Q104.9@5446.46,2315.32 Q104.9@5446.46,2367.68 Q105.9@5344.29,1771.91 Q105.9@5344.29,1958.72 Q105.9@5355.91,1812.95 Q105.9@5355.91,1865.32 Q105.9@5355.91,1917.68 Q105.9@5401.18,1812.95 Q105.9@5401.18,1865.32 Q105.9@5401.18,1917.68 Q105.9@5406.5,1865.32 Q105.9@5446.46,1812.95 Q105.9@5446.46,1865.32 Q105.9@5446.46,1917.68 Q106.9@5344.29,2446.91 Q106.9@5344.29,2633.72 Q106.9@5355.91,2487.95 Q106.9@5355.91,2540.32 Q106.9@5355.91,2592.68 Q106.9@5401.18,2487.95 Q106.9@5401.18,2540.32 Q106.9@5401.18,2592.68 Q106.9@5406.5,2540.32 Q106.9@5446.46,2487.95 Q106.9@5446.46,2540.32 Q106.9@5446.46,2592.68 Q107.9@5344.29,1996.91 Q107.9@5344.29,2183.72 Q107.9@5355.91,2037.95 Q107.9@5355.91,2090.32 Q107.9@5355.91,2142.68 Q107.9@5401.18,2037.95 Q107.9@5401.18,2090.32 Q107.9@5401.18,2142.68 Q107.9@5406.5,2090.32 Q107.9@5446.46,2037.95 Q107.9@5446.46,2090.32 Q107.9@5446.46,2142.68 RT200.1S RT200.2S U100.8 U100.13 U101.8 U101.9@1430,1682.28 U101.9@1430,1717.72 U201.8 U201.9@2257.17,406.22 U201.9@2257.17,441.65 U203.4 U204.4
copper on no net:
  other v1: 1109.65,3287.73 1109.65,3886.16
  other v2: 5624.29,932.74 5584.92,933.74 5663.66,933.74

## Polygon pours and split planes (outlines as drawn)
VBB on Bottom Layer "VBB" (solid, remove dead copper, pour order 784): 645.67,425.2 629.92,440.94 629.92,3169.29 649.61,3188.98 964.57,3188.98 984.25,3169.29 984.25,3059.06 1062.99,2980.31 1062.99,1889.76 1062.99,440.94 1047.24,425.2
PGND on Bottom Layer "PGND" (solid, remove dead copper, pour order 772): 1929.13,2818.9 1913.39,2803.15 1913.39,2161.42 1988.19,2086.61 2106.3,2086.61 2125.98,2106.3 2125.98,2799.21 2106.3,2818.9
PGND on Bottom Layer "PGND" (solid, remove dead copper, pour order 762): 1062.99,3346.46 944.88,3228.35 633.86,3228.35 606.3,3200.79 606.3,736.22 531.5,661.42 531.5,492.13 433.07,393.7 137.8,393.7 39.37,492.13 39.37,3440.94 145.67,3547.24 1374.02,3547.24 1452.76,3625.98 1452.76,3901.57 1464.57,3913.39 1653.54,3913.39 1669.29,3897.64 1669.29,3125.98 1653.54,3110.24 1472.44,3110.24 1448.82,3133.86 1448.82,3322.83 1425.2,3346.46
VBB on Bottom Layer "VBB" (solid, remove dead copper, pour order 760): 1543.31,2822.83 1484.25,2763.78 1484.25,2263.78 1661.42,2086.61 1787.4,2086.61 1862.2,2161.42 1862.2,2803.15 1842.52,2822.83
SWNODE2 on Bottom Layer "SWNODE2" (solid, remove dead copper, pour order 746): 1236.22,3307.09 1220.47,3291.34 1220.47,3039.37 1283.46,2976.38 1354.33,2976.38 1417.32,3039.37 1417.32,3291.34 1401.57,3307.09
SWNODE1 on Bottom Layer "SWNODE1" (solid, remove dead copper, pour order 738): 1236.22,3913.39 1220.47,3897.64 1220.47,3645.67 1283.46,3582.68 1354.33,3582.68 1417.32,3645.67 1417.32,3897.64 1401.57,3913.39
VBB1 on Bottom Layer "VBB1" (solid, remove dead copper, pour order 722): 1811.02,3917.32 1771.65,3877.95 1771.65,3141.73 1811.02,3102.36 1984.25,3102.36 2023.62,3141.73 2023.62,3877.95 1984.25,3917.32
SWNODE3 on Bottom Layer "SWNODE3" (solid, remove dead copper, pour order 688): 5482.91,3308.43 5362.2,3429.13 5362.2,3665.35 5318.9,3708.66 4771.65,3708.66 4748.03,3732.28 4748.03,4078.74 4767.72,4098.43 5555.12,4098.43 5570.87,4082.68 5570.87,3733.11 5590.55,3713.43 5896.38,3713.43 5931.38,3748.43 5931.38,4123.43 5946.38,4138.43 6056.38,4138.43 6146.38,4048.43 6146.38,3438.43 6016.38,3308.43
SWNODE4 on Bottom Layer "SWNODE4" (solid, remove dead copper, pour order 686): 5726.38,3177.17 5724.41,3179.13 5724.41,3255.91 5531.5,3448.82 5314.96,3665.35 4771.65,3665.35 4748.03,3641.73 4748.03,3299.21 4771.65,3275.59 5326.77,3275.59 5338.58,3263.78 5338.58,3050.65 5605.56,2783.43 5706.38,2783.43 5726.38,2803.43
VSR on Bottom Layer "VSR" (solid, remove dead copper, pour order 229): 3175.98,2050 3160,2034.02 3160,1445 3170,1435 4250,1435 4409.45,1594.45 4409.45,2007.87 4367.32,2050
NetL103_1 on Bottom Layer "L103_1" (solid, remove dead copper, pour order 210): 1400,1705 1400,1720 1380,1720 1370,1730 1370,1760 1360,1770 1220,1770 1210,1760 1210,1715 1220,1705
5Vp on Bottom Layer "5Vp" (solid, remove dead copper, pour order 209): 1220,1700 1210,1690 1210,1525 1295,1440 1370,1440 1380,1450 1380,1675 1385,1680 1400,1680 1400,1695 1350,1695 1345,1700
12Vp on Bottom Layer "12Vp" (solid, remove dead copper, pour order 207): 1575,1355 1675,1355 1710,1320 1750,1320 1760,1330 1760,1670 1715,1715 1460,1715 1460,1685 1480,1685 1570,1595 1570,1360
SGND on Bottom Layer "SGND" (solid, remove dead copper, pour order 202): 6192.91,1750 6234.25,1750 6255.91,1771.65 6255.91,1964.57 6271.65,1980.32 6598.43,1980.32 6598.43,1208.66 6594.49,1208.66 6193.29,1208.29 6115,1130 5505,1130 5449.8,1074.8 4803.15,1074.8 4785,1092.95 4785,1675 4860,1750 5425,1750 5465,1710 5580,1710 5620,1750
54V1 on Bottom Layer "54V1" (solid, remove dead copper, pour order 100): 5122.05,2633.86 5110.24,2622.05 5110.24,1779.53 5129.92,1759.84 5267.72,1759.84 5287.4,1779.53 5287.4,2574.8 5228.35,2633.86
54V1 on Bottom Layer "54V1" (solid, remove dead copper, pour order 112): 5594.49,1039.37 5590.55,1035.43 5590.55,988.19 5618.11,988.19 5618.11,1035.43 5614.17,1039.37
54V2 on Bottom Layer "54V2" (solid, remove dead copper, pour order 116): 6244.09,2610.24 6267.72,2586.61 6598.43,2586.61 6598.43,2007.87 6271.65,2007.87 6244.09,1980.32 6244.09,1775.59 6228.35,1759.84 5350.39,1759.84 5330.71,1779.53 5330.71,2645.67 5350.39,2665.35 6224.41,2665.35 6244.09,2645.67
Iout_SNS on Bottom Layer "Iout_SNS" (solid, remove dead copper, pour order 189): 4515.75,2748.03 4547.24,2716.54 4858.27,2716.54 4878.05,2696.95 4895,2680 4895,2520 4915,2500 5000,2500 5015,2485 5015,1944.13 4724.41,1653.54 4645.67,1653.54 4515.75,1783.46 4515.75,2064.25 4430.39,2149.61 4114.17,2465.83 4114.17,2759.84 4259.81,2905.48 4437.01,2905.51 4515.75,2826.77
SGND on Bottom Layer "SGND" (solid, remove dead copper, pour order 201): 4900,2540 4925,2515 5000,2515 5015,2530 5015,2835 4940,2910 4575,2910 4530,2865 4530,2755 4555,2730 4870,2730 4900,2700
PGND on Bottom Layer "PGND" (solid, remove dead copper, pour order 255): 1640,1140 1260,1140 1180,1139.99 1135,1185 1135,1755 1450,2070 1620,2070 1730,1960 1730,1190 1680,1140
SGND on Bottom Layer "SGND" (solid, remove dead copper, pour order 580): 2299.21,1248.03 3574.8,1248.03 3574.8,755.91 4019.69,755.91 4322.83,1059.05 6192.91,1059.06 6232.28,1019.68 6232.28,35.43 6196.85,0 1910,0 1586.61,0 1559.06,31.5 1559.05,980.32 1724.41,1145.67 1925.2,1346.46 2200.79,1346.46
SGND on Bottom Layer "SGND" (solid, remove dead copper, pour order 600): 4255.91,1417.32 4055.12,1417.32 4043.31,1405.51 4043.31,1291.34 4035.43,1283.46 2263.78,1283.46 2263.78,775.59 4011.81,775.59 4311.02,1074.8 4814.96,1074.8 4814.96,1669.29 4803.15,1681.1 4791.34,1681.1 4755.91,1645.67 4484.25,1645.67
PGND on Top Layer "PGND" (solid, remove dead copper, pour order 792): 586.61,2956.69 625.98,2956.69 1519.68,2062.99 1519.68,1433.07 1484.25,1397.64 1224.41,1397.64 629.92,1992.13 629.92,2622.05 582.68,2622.05
PGND on Top Layer "PGND" (solid, remove dead copper, pour order 774): 1929.13,2818.9 1913.39,2803.15 1913.39,2161.42 1988.19,2086.61 2106.3,2086.61 2125.98,2106.3 2125.98,2799.21 2106.3,2818.9
PGND on Top Layer "PGND" (solid, remove dead copper, pour order 756): 1062.99,3346.46 944.88,3228.35 633.86,3228.35 606.3,3200.79 606.3,736.22 531.5,661.42 531.5,492.13 433.07,393.7 137.8,393.7 39.37,492.13 39.37,3440.94 145.67,3547.24 1374.02,3547.24 1452.76,3625.98 1452.76,3901.57 1464.57,3913.39 1653.54,3913.39 1669.29,3897.64 1669.29,3125.98 1653.54,3110.24 1472.44,3110.24 1448.82,3133.86 1448.82,3322.83 1425.2,3346.46
SWNODE2 on Top Layer "SWNODE2" (solid, remove dead copper, pour order 744): 1236.22,3307.09 1220.47,3291.34 1220.47,3039.37 1283.46,2976.38 1354.33,2976.38 1417.32,3039.37 1417.32,3291.34 1401.57,3307.09
SWNODE1 on Top Layer "SWNODE1" (solid, remove dead copper, pour order 732): 1236.22,3913.39 1220.47,3897.64 1220.47,3645.67 1283.46,3582.68 1354.33,3582.68 1417.32,3645.67 1417.32,3897.64 1401.57,3913.39
VBB1 on Top Layer "VBB1" (solid, remove dead copper, pour order 720): 1811.02,3917.32 1771.65,3877.95 1771.65,3141.73 1811.02,3102.36 1984.25,3102.36 2023.62,3141.73 2023.62,3877.95 1984.25,3917.32
VBB on Top Layer "VBB" (solid, remove dead copper, pour order 718): 1543.31,2822.83 1263.78,2822.83 913.39,3173.23 661.42,3173.23 653.54,3165.35 653.54,2972.44 1019.69,2606.3 1267.72,2606.3 1484.25,2389.76 1484.25,2263.78 1661.42,2086.61 1787.4,2086.61 1811.02,2110.24 1811.02,2795.28 1783.46,2822.83
SWNODE4 on Top Layer "SWNODE4" (solid, remove dead copper, pour order 696): 5726.38,3177.17 5724.41,3179.13 5724.41,3255.91 5531.5,3448.82 5531.5,3566.93 5433.07,3665.35 4771.65,3665.35 4748.03,3641.73 4748.03,3299.21 4771.65,3275.59 5326.77,3275.59 5338.58,3263.78 5338.58,3050.65 5605.56,2783.43 5706.38,2783.43 5726.38,2803.43
SWNODE4 on Top Layer "SWNODE4" (solid, remove dead copper, pour order 694): 5921.38,4123.43 5906.38,4138.43 5756.38,4138.43 5741.38,4123.43 5741.38,3563.43 5921.38,3383.43 5921.38,2818.43 5941.38,2798.43 6056.38,2798.43 6076.38,2818.43 6076.38,3593.43 5921.38,3748.43
SWNODE3 on Top Layer "SWNODE3" (solid, remove dead copper, pour order 692): 5546.38,4123.43 5561.38,4138.43 5711.38,4138.43 5726.38,4123.43 5726.38,3553.43 5906.38,3373.43 5906.38,2818.43 5886.38,2798.43 5776.38,2798.43 5756.38,2818.43 5756.38,3243.62 5546.38,3453.62
SWNODE3 on Top Layer "SWNODE3" (solid, remove dead copper, pour order 690): 5338.58,4098.43 4748.03,4098.43 4748.03,3708.66 5338.58,3708.66
12Vp on Top Layer "12Vp" (solid, remove dead copper, pour order 208): 1570,1355 1560,1365 1560,1695 1290,1965 1290,2050 1300,2060 1360,2060 1760,1660 1760,1455 1660,1355
NetL200_1 on Top Layer "L200_1" (solid, remove dead copper, pour order 160): 2302.72,430.2 2460.2,430.2 2475.94,445.94 2475.94,512.87 2472.01,516.81 2342.09,516.81 2338.15,512.87 2338.15,469.57 2302.72,434.13
5Vs on Top Layer "5Vs" (solid, remove dead copper, pour order 154): 2342.09,430.2 2342.09,379.02 2318.46,355.39 2318.46,300.28 2326.34,292.4 2428.7,292.4 2472.01,335.71 2472.01,430.2
SGND on Top Layer "SGND" (solid, remove dead copper, pour order 177): 2299.21,1248.03 3574.8,1248.03 3574.8,751.97 4007.87,751.97 4314.96,1059.05 6192.91,1059.06 6232.28,1019.68 6232.28,35.43 6196.85,0 1910,0 1586.61,0 1559.06,31.5 1559.06,1129.92 1574.8,1145.67 1724.41,1145.67 1925.2,1346.46 2200.79,1346.46
SGND on Top Layer "SGND" (solid, remove dead copper, pour order 179): 4732.28,1645.67 4484.25,1645.67 4255.91,1417.32 4055.12,1417.32 4043.31,1405.51 4043.31,1342.52 3980.31,1279.53 2263.78,1279.53 2255.91,1271.65 2255.91,1169.29 2649.61,775.59 4014.96,775.59 4308.73,1074.8 4909.45,1074.8 5047.24,1074.8 5062.99,1074.8 5307.27,1074.8 6192.91,1074.8 6236.22,1118.11 6326.77,1208.66 6602.36,1208.66 6602.36,1783.46 6295.28,1783.46 6236.22,1724.41 5594.49,1724.41 5578.74,1708.66 5452.76,1708.66 5417.32,1744.09 5125.98,1744.09 5102.36,1767.72 5102.36,2586.61 5047.24,2641.73 5045,2641.73 4766.73,2920 4690,2920 4595,3015 3960,3015 3920,2975 3920,2910 3963.86,2866.14 4153.54,2866.14 4212.6,2925.2 4486.87,2925.2 4911.69,2501.69 4940.94,2472.44 4940.94,1854.33
54V1 on Top Layer "54V1" (solid, remove dead copper, pour order 102): 5122.05,2633.86 5110.24,2622.05 5110.24,1779.53 5129.92,1759.84 5267.72,1759.84 5287.4,1779.53 5287.4,2622.05 5275.59,2633.86
54V2 on Top Layer "54V2" (solid, remove dead copper, pour order 106): 6244.09,2610.24 6267.72,2586.61 6602.36,2586.61 6602.36,1811.02 6279.53,1811.02 6228.35,1759.84 5350.39,1759.84 5330.71,1779.53 5330.71,2645.67 5350.39,2665.35 6224.41,2665.35 6244.09,2645.67
Iout_SNS on Top Layer "Iout_SNS" (solid, remove dead copper, pour order 108): 4854.33,2488.19 4905.51,2488.19 4929.13,2464.57 4929.13,1858.27 4724.41,1653.54 4645.67,1653.54 4637.8,1661.42 4637.8,2110.24 4318.03,2430 4251.1,2430 4196.85,2484.25 4196.85,2842.52 4255.91,2901.57 4440.94,2901.57
12Vs on Top Layer "12Vs" (solid, remove dead copper, pour order 54): 1948.82,122.05 1925.2,145.67 1925.2,374.02 2015.75,464.57 2181.1,464.57 2188.98,456.69 2188.98,413.39 2181.1,405.51 2102.36,405.51 2039.37,342.52 2039.37,161.42 2000,122.05
SGND on Signal Layer 1 "SGND" (solid, remove dead copper, pour order 788): 2263.78,3976.38 2204.72,3917.32 2204.72,3090.55 2244.09,3051.18 4303.15,3051.18 4940.94,2413.39 4940.94,1830.71 4885.83,1775.59 4885.83,1078.74 4889.76,1074.8 6196.85,1074.8 6244.09,1122.05 6244.09,1732.28 6228.35,1748.03 5125.98,1748.03 5098.43,1775.59 5098.43,2629.92 5145.67,2677.17 6051.18,2677.17 6062.99,2688.98 6062.99,2732.28 6047.24,2748.03 5543.31,2748.03 5283.46,3007.87 5283.46,3181.1 5248.03,3216.54 4696.85,3216.54 4685.04,3228.35 4685.04,4015.75 4566.93,4133.86 2421.26,4133.86
PGND on Signal Layer 1 "PGND" (solid, remove dead copper, pour order 770): 1062.99,3346.46 944.88,3228.35 633.86,3228.35 606.3,3200.79 606.3,736.22 531.5,661.42 531.5,492.13 433.07,393.7 137.8,393.7 39.37,492.13 39.37,3440.94 145.67,3547.24 1374.02,3547.24 1452.76,3625.98 1452.76,3901.57 1464.57,3913.39 1653.54,3913.39 1669.29,3897.64 1669.29,3125.98 1653.54,3110.24 1472.44,3110.24 1448.82,3133.86 1448.82,3322.83 1425.2,3346.46
SWNODE2 on Signal Layer 1 "SWNODE2" (solid, remove dead copper, pour order 754): 1236.22,3307.09 1220.47,3291.34 1220.47,3039.37 1283.46,2976.38 1354.33,2976.38 1417.32,3039.37 1417.32,3291.34 1401.57,3307.09
SWNODE1 on Signal Layer 1 "SWNODE1" (solid, remove dead copper, pour order 742): 1236.22,3913.39 1220.47,3897.64 1220.47,3645.67 1283.46,3582.68 1354.33,3582.68 1417.32,3645.67 1417.32,3897.64 1401.57,3913.39
VBB1 on Signal Layer 1 "VBB1" (solid, remove dead copper, pour order 730): 1811.02,3917.32 1771.65,3877.95 1771.65,3141.73 1811.02,3102.36 1984.25,3102.36 2023.62,3141.73 2023.62,3877.95 1984.25,3917.32
VBB on Signal Layer 1 "VBB" (solid, remove dead copper, pour order 714): 645.67,425.2 629.92,440.94 629.92,3169.29 649.61,3188.98 964.57,3188.98 984.25,3169.29 984.25,3059.06 1248.03,2795.28 1661.42,2795.28 1700.79,2755.91 1700.79,2165.35 1661.42,2125.98 1299.21,2125.98 1062.99,1889.76 1062.99,440.94 1047.24,425.2
SWNODE3 on Signal Layer 1 "SWNODE3" (solid, remove dead copper, pour order 698): 5482.91,3308.43 5362.2,3429.13 5362.2,3665.35 5318.9,3708.66 4771.65,3708.66 4748.03,3732.28 4748.03,4078.74 4767.72,4098.43 5519.69,4098.43 5570.87,4047.24 5570.87,3733.11 5590.55,3713.43 5896.38,3713.43 5931.38,3748.43 5931.38,4123.43 5946.38,4138.43 6056.38,4138.43 6146.38,4048.43 6146.38,3438.43 6016.38,3308.43
VSR on Signal Layer 1 "VSR" (solid, remove dead copper, pour order 628): 3335,2050 3160,1875 3160,1445 3170,1435 4250,1435 4409.45,1594.45 4409.45,2007.87 4367.32,2050
PGND on Signal Layer 1 "PGND" (solid, remove dead copper, pour order 222): 1640,1140 1260,1140 1180,1139.99 1135,1185 1135,1755 1450,2070 1620,2070 1730,1960 1730,1190 1680,1140
54V1 on Signal Layer 1 "54V1" (solid, remove dead copper, pour order 176): 5122.05,2633.86 5110.24,2622.05 5110.24,1779.53 5129.92,1759.84 5267.72,1759.84 5287.4,1779.53 5287.4,2622.05 5275.59,2633.86
54V2 on Signal Layer 1 "54V2" (solid, remove dead copper, pour order 142): 6228.35,1759.84 6244.09,1775.59 6244.09,2645.67 6224.41,2665.35 5350.39,2665.35 5330.71,2645.67 5330.71,1779.53 5350.39,1759.84
Iout_SNS on Signal Layer 1 "Iout_SNS" (solid, remove dead copper, pour order 134): 4854.33,2488.19 4905.51,2488.19 4929.13,2464.57 4929.13,1858.27 4724.41,1653.54 4645.67,1653.54 4515.75,1783.46 4515.75,2062.99 4114.17,2464.57 4114.17,2759.84 4259.84,2905.51 4437.01,2905.51
SGND on Signal Layer 1 "SGND" (solid, remove dead copper, pour order 588): 2299.21,1248.03 3574.8,1248.03 3574.8,751.97 4019.69,751.97 4326.77,1059.05 6192.91,1059.06 6232.28,1019.68 6232.28,35.43 6196.85,0 1910,0 1586.61,0 1559.06,31.5 1559.05,980.32 1724.41,1145.67 1925.2,1346.46 2200.79,1346.46
SGND on Signal Layer 1 "SGND" (solid, remove dead copper, pour order 614): 4255.91,1417.32 4055.12,1417.32 4043.31,1405.51 4043.31,1291.34 4035.43,1283.46 2248.03,1283.46 2248.03,775.59 4007.87,775.59 4307.09,1074.8 4917.32,1074.8 4917.32,1783.46 4893.7,1783.46 4755.91,1645.67 4484.25,1645.67
VBB on Signal Layer 2 "VBB" (solid, remove dead copper, pour order 780): 1232.28,2818.9 877.95,3173.23 661.42,3173.23 653.54,3165.35 653.54,2972.44 1019.69,2606.3 1539.37,2086.61 1787.4,2086.61 1811.02,2110.24 1811.02,2795.28 1787.4,2818.9
PGND on Signal Layer 2 "PGND" (solid, remove dead copper, pour order 768): 1062.99,3346.46 944.88,3228.35 633.86,3228.35 606.3,3200.79 606.3,736.22 531.5,661.42 531.5,492.13 433.07,393.7 137.8,393.7 39.37,492.13 39.37,3440.94 145.67,3547.24 1374.02,3547.24 1452.76,3625.98 1452.76,3901.57 1464.57,3913.39 1653.54,3913.39 1669.29,3897.64 1669.29,3125.98 1653.54,3110.24 1472.44,3110.24 1448.82,3133.86 1448.82,3322.83 1425.2,3346.46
